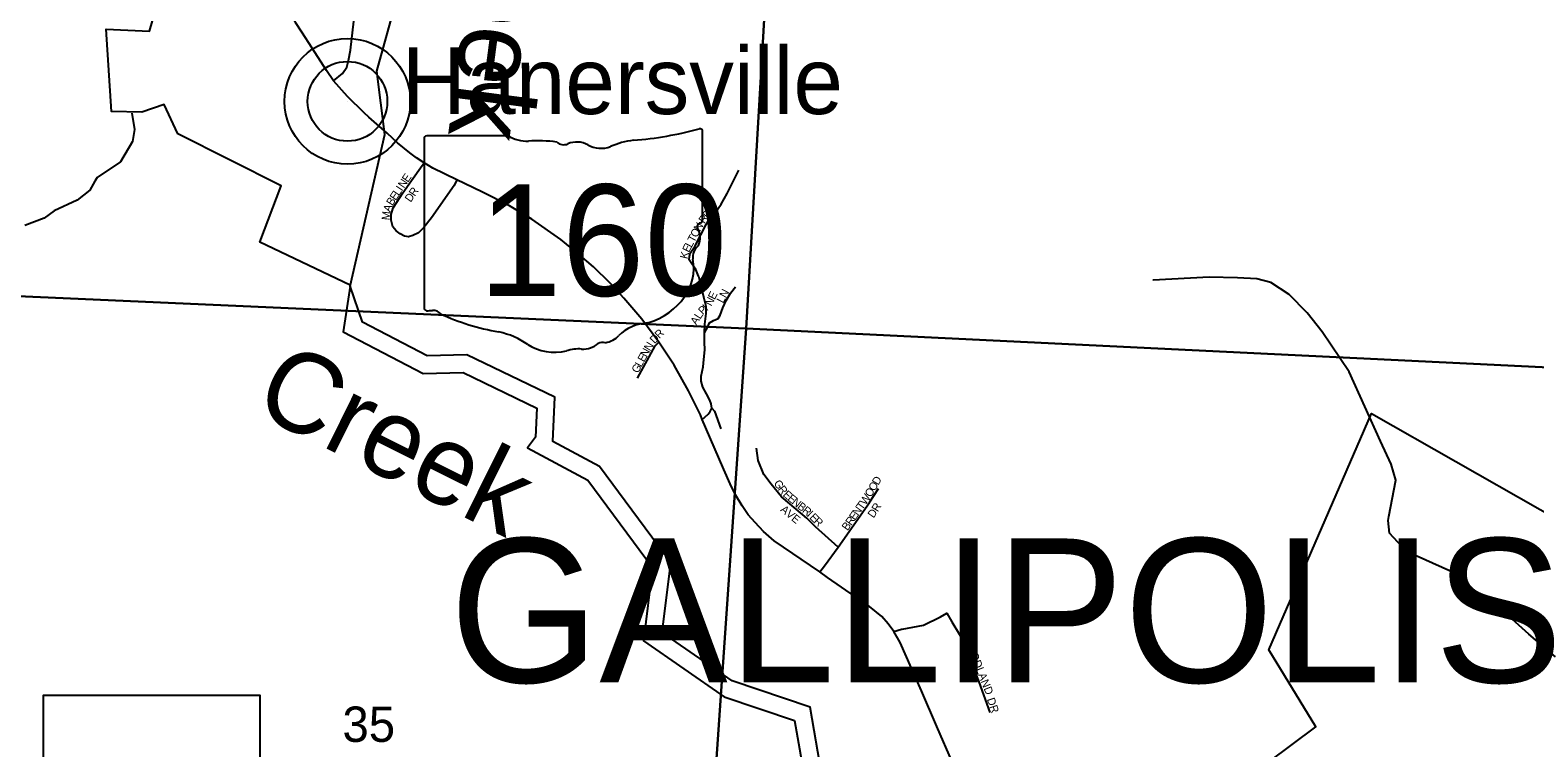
# Model space of a CAD drawing. Extents: x 1878108 to 2183446, y 146837 to 508383.
# Drawn here: x 2047624 to 2057027, y 300413 to 304899 of the extents above; entities that cross this region are included whole.
import ezdxf

# ---------------------------------------------------------------- set-up
doc = ezdxf.new("R2010")
doc.units = 0
for name, color, linetype in [('GM_X_Corporation', 7, 'Continuous'), ('GM_X_County_Road', 7, 'Continuous'), ('GM_X_Minor_River', 7, 'Continuous'), ('GM_X_Minor_River_Text', 7, 'Continuous'), ('GM_X_Section', 7, 'Continuous'), ('GM_X_Section_Text', 7, 'Continuous'), ('GM_X_State_Location', 7, 'Continuous'), ('GM_X_State_Route', 7, 'Continuous'), ('GM_X_State_Shield', 7, 'Continuous'), ('GM_X_Township_Subdivision', 7, 'Continuous'), ('GM_X_Township_Subdivision_Text', 7, 'Continuous'), ('GM_X_Township_Text', 7, 'Continuous'), ('GM_X_Unincorporated', 7, 'Continuous'), ('GM_X_Unincorporated_Location', 7, 'Continuous'), ('GM_X_Unincorporated_Text', 7, 'Continuous')]:
    doc.layers.add(name, color=color, linetype=linetype)

msp = doc.modelspace()

# ---------------------------------------------------------------- linework, layer by layer
at = {"layer": 'GM_X_Corporation'}
for points in [[(2052438.4, 298141.1), (2055657.4, 300543.5), (2055364.1, 301025.2), (2056004.9, 302502.4), (2057587.6, 301603.3)], [(2047707.8, 297853.1), (2047707.7, 300742.9), (2049060.7, 300742.9), (2049060.7, 300300.3)]]:
    msp.add_lwpolyline(points, dxfattribs=at)
at = {"layer": 'GM_X_County_Road'}
msp.add_lwpolyline([(2049520.9, 304582.1), (2049576.5, 304628.2), (2049602.6, 304667.2), (2049614.4, 304708.6), (2049626.2, 304773.7), (2049646.3, 304955.9), (2049667.6, 305345.1), (2049683, 305649.1), (2049706.7, 306075), (2049716.1, 306250.1), (2049732.7, 306522.2), (2049753.9, 306853.8), (2049757.2, 306919.2), (2049764.7, 307070.1), (2049782.4, 307328.9), (2049784.6, 307463.8), (2049773.6, 307593.1), (2049772.1, 307646.4)], dxfattribs=at)
at = {"layer": 'GM_X_Minor_River'}
for points in [[(2049624.7, 303298.8), (2049841.3, 304246.1), (2049790, 304642.5), (2049918.2, 305102.6), (2050045.4, 305183.9), (2050030.3, 305570.6), (2050133.2, 305673.7), (2050185.2, 306139.2), (2050274.7, 307106), (2049923.1, 307624), (2050030, 308031.8), (2050142.8, 308293.3), (2050473.9, 308424.6), (2050730.9, 308841.8), (2050918.4, 309368.5), (2051262.7, 309860.7), (2051316.1, 309921.3), (2051714.1, 310442), (2051728.6, 310861), (2051598.1, 311944.1)], [(2049625.1, 303304.3), (2049060.4, 303573.8), (2049194, 303925.7), (2048546.4, 304250.6), (2048461.8, 304434.2), (2048322.1, 304386.8), (2048133.6, 304391.2), (2048098.8, 304905.9), (2048369.6, 304892.3), (2048427.1, 305087.2), (2048322.9, 305545.3), (2048043, 305791.3), (2047766.3, 305957.2), (2047698.3, 306247.2), (2047932.5, 306575.9), (2047894.8, 306697.9), (2047830, 306749.4), (2047573.1, 306929.5)], [(2048260.7, 304380.1), (2048276.7, 304277.7), (2048264.7, 304203.4), (2048188.6, 304076.8), (2048042.4, 303978.3), (2048028.4, 303954.2), (2047998.4, 303898), (2047918.3, 303835.6), (2047774.2, 303769.2), (2047712.1, 303723), (2047592, 303678.7)], [(2057155.9, 300981.2), (2056989.9, 301123.5), (2056883.8, 301217.8), (2056747.7, 301301.9), (2056507.7, 301512.5), (2056225.5, 301640.6), (2056117.5, 301754.9), (2056109.5, 301833.2), (2056113.5, 301859.3), (2056157.6, 302086.2), (2056129.6, 302186.5), (2056061.6, 302329), (2055865.6, 302762.4), (2055697.6, 303013.1), (2055603.6, 303131.5), (2055491.6, 303245.8), (2055377.5, 303321.9), (2055289.5, 303343.9), (2055169.4, 303349.8), (2054991.3, 303355.6), (2054641, 303337.2), (2054640.4, 303337)], [(2049624.4, 303299.6), (2049580.9, 303013.3), (2050079.4, 302753.2), (2050329.8, 302759.5), (2050789.8, 302537.1), (2050782.1, 302354.7), (2050732.9, 302288.1), (2051108.4, 302087.1), (2051512.4, 301539.6), (2051456.3, 301082.2), (2051962, 300732), (2052400.9, 300583.7), (2052470.3, 300181.5), (2052587.8, 300088.4), (2052896.3, 299946.9), (2052822.2, 299789.9), (2052879.2, 299726.3), (2053136.6, 299664.5), (2053130.2, 299538.2), (2053120.8, 299337.7), (2053342.7, 299079.2), (2053250.6, 298688.9)], [(2053357.7, 298663.7), (2053462.6, 299108.4), (2053232.7, 299376.2), (2053240.1, 299532.8), (2053251, 299750.1), (2052958.3, 299820.4), (2053043.3, 300000.5), (2052645.7, 300182.8), (2052571.6, 300241.6), (2052498.2, 300666.9), (2052011.9, 300831.3), (2051573.6, 301134.8), (2051626.9, 301569.7), (2051182.1, 302172.3), (2050891.1, 302328.2), (2050902.7, 302604.7), (2050353.7, 302870.1), (2050105, 302863.9), (2049701.4, 303074.4), (2049624.4, 303299.6)]]:
    msp.add_lwpolyline(points, dxfattribs=at)
at = {"layer": 'GM_X_Section'}
for points in [[(2052415.9, 308472), (2052098.8, 303033.5), (2046608.5, 303278.4), (2046921.6, 308750.8)], [(2057942.3, 308221.2), (2057916.7, 307664.9), (2057890.5, 307119.5), (2057859.5, 306520.8), (2057833, 305974.8), (2057806.5, 305428.7), (2057761.9, 304523.6), (2057716.2, 303631), (2057671.2, 302762.9), (2052098.8, 303033.5), (2052415.9, 308472)], [(2046608.5, 303278.4), (2052098.8, 303033.5), (2051725.6, 297626.8), (2046305.3, 297866)], [(2057671.2, 302762.9), (2057670.5, 302747.5), (2057409.6, 297482.6), (2057317.7, 297440.2), (2057229.7, 297429.9), (2057149.7, 297419.7), (2057045.8, 297401.3), (2056985.8, 297385.1), (2056929.8, 297374.9), (2051725.6, 297626.8), (2052098.8, 303033.5)]]:
    msp.add_lwpolyline(points, close=True, dxfattribs=at)
at = {"layer": 'GM_X_State_Route'}
for points in [[(2049321.7, 304886.1), (2049283.2, 304946.4), (2049201.5, 305068.3), (2049124.6, 305166.5), (2048998.1, 305304.9), (2048854.9, 305461.3), (2048701.1, 305623.7), (2048439.5, 305905.2)], [(2050338.6, 303940), (2050290.8, 303962.8), (2050140.8, 304036.7), (2050086.4, 304070.2), (2050037.9, 304101.8), (2049997.7, 304131.3), (2049920.8, 304194), (2049855.7, 304254.4), (2049740.1, 304355.2), (2049711.4, 304382.1), (2049607.3, 304483.9), (2049520.9, 304582.1), (2049476, 304645.9), (2049386.1, 304785.5), (2049321.7, 304886.1)], [(2053388.2, 300322.1), (2053288.8, 300546.8), (2053194.2, 300770.4), (2053060.5, 301070.9), (2053020.3, 301139.5), (2052984.8, 301189.2), (2052945.7, 301233), (2052870, 301296.9), (2052606.2, 301478.7), (2052559.1, 301512.5), (2052273.8, 301706.2), (2052207.5, 301765.3), (2052154.3, 301820.9), (2052111.7, 301869.4), (2052073.9, 301925), (2052032.5, 301993.7), (2051998.1, 302063.4), (2051957.9, 302153.4), (2051898.8, 302293), (2051824.2, 302466.3), (2051812.4, 302494), (2051739.1, 302645.5), (2051648, 302804), (2051552.2, 302948.3), (2051445.7, 303092.7), (2051334, 303224.6), (2051248.1, 303317.4), (2051144, 303419.2), (2051046.8, 303502.9), (2050940.5, 303590.7), (2050758.4, 303717.3), (2050619.9, 303800.1), (2050450.8, 303886.5), (2050338.6, 303940)]]:
    msp.add_lwpolyline(points, dxfattribs=at)
at = {"layer": 'GM_X_State_Shield'}
for p, q in [((2050086, 304220.4), (2050086, 303163.7)), ((2050612.8, 304238.6), (2050103.1, 304238.6)), ((2051826.2, 303712), (2051826.2, 304264.7)), ((2051826, 303712.1), (2051826.2, 303712))]:
    msp.add_line(p, q, dxfattribs=at)
for centre, major_axis, start_param, end_param in [((2051206.3, 305679.1), (1845.5, 0), 4.814394, 5.042369), ((2051806.9, 304267), (19.4, 0), 6.141152, 7.989035), ((2050105.9, 304222.6), (20.2, 0), 1.712693, 3.28349), ((2050734.1, 304361.2), (195.5, 0), 4.042523, 4.731795), ((2050799, 303645.4), (702, 0), 1.404758, 1.657858), ((2050958.3, 304228.1), (56.4, 0), 3.836095, 5.185415), ((2051041.2, 304106), (117.3, 0), 0.950623, 2.079405), ((2051192.5, 304273.5), (141.1, 0), 4.081561, 5.145723), ((2051441.7, 303915.8), (371.3, 0), 1.699011, 2.107814), ((2051805.5, 303709.9), (20.7, 0), 5.05454, 6.418171), ((2051821.7, 303671.4), (30, 0), 1.883978, 3.671073), ((2051631, 303601.6), (180, 0), 5.934695, 6.695948), ((2051895.6, 303480.7), (130.9, 0), 2.387724, 3.262537), ((2051309.7, 303410.4), (461.6, 0), 5.101752, 6.440018), ((2050106.1, 303161.4), (20.3, 0), 3.00124, 4.508301), ((2050109.2, 303269.5), (155.2, 0), 4.665946, 4.897461), ((2050141, 303102.8), (56, 0), 0.519207, 1.627899), ((2050847.6, 304052.1), (1332.7, 0), 4.195997, 4.488961), ((2051504.3, 302867.1), (252.8, 0), 1.647645, 2.488434), ((2050450.2, 302689), (417, 0), 0.823519, 1.323587), ((2051184, 303061.3), (149.1, 0), 4.937069, 5.64225), ((2050901.2, 303097.5), (264.6, 0), 4.026481, 4.996735), ((2051054.1, 302732.2), (217.4, 0), 1.495662, 1.94098), ((2051073.4, 303018.4), (141, 0), 4.691044, 5.507374), ((2051201, 302916.1), (39.7, 0), 1.147584, 2.315152)]:
    msp.add_ellipse(centre, major_axis=major_axis, ratio=0.8, start_param=start_param, end_param=end_param, dxfattribs=at)
at = {"layer": 'GM_X_Township_Subdivision'}
for points in [[(2050290.8, 303962.8), (2050273.3, 303927.9), (2050132.6, 303725.6), (2050085.2, 303665.2), (2050050.9, 303632.1), (2050016.6, 303615.5), (2049989.4, 303607.3), (2049962.6, 303611.9), (2049937.4, 303625), (2049911.3, 303643.9), (2049891.2, 303670), (2049879.4, 303711.4), (2049880.6, 303746.9), (2049893.6, 303788.3), (2049952.7, 303881.7), (2050008.3, 303959.8), (2050073.4, 304053.3), (2050086.4, 304070.2)], [(2051800.9, 303362.2), (2051784, 303403.8), (2051759.2, 303438.1), (2051742.6, 303464.1), (2051743.8, 303484.2), (2051748.5, 303504.3), (2051779.3, 303551.7), (2051847.9, 303684.2), (2051870.4, 303719.7), (2051909.5, 303763.5), (2051941.4, 303811.9), (2051980.4, 303877), (2052052.6, 304023.7)], [(2051859.2, 302497.3), (2051860.9, 302498.8), (2051873.9, 302515.4), (2051883.4, 302536.6), (2051879.8, 302562.7), (2051871.6, 302585.2), (2051850.3, 302626.6), (2051827.8, 302666.8), (2051818.3, 302704.6), (2051818.3, 302735.4), (2051829, 302794.5), (2051833.7, 302839.5), (2051840.2, 302901.5), (2051837.3, 302948.3), (2051837.3, 303007.5), (2051840.8, 303061.9), (2051847.9, 303128.2), (2051849.1, 303170.7), (2051834.7, 303231), (2051816, 303309.1), (2051801.8, 303360), (2051800.9, 303362.2)], [(2051837.3, 303007.5), (2051856.2, 303039.4), (2051870.4, 303069), (2051895.2, 303084.4), (2051923.6, 303097.4), (2051936.6, 303117.5), (2051952, 303162.5), (2051974.5, 303208.6), (2052000.5, 303255.9), (2052031.3, 303293.8)], [(2051418.5, 302723.6), (2051529.7, 302925.9), (2051552.2, 302948.3)], [(2051824.2, 302466.3), (2051859.2, 302497.3)], [(2051883.4, 302536.6), (2051901.1, 302517.7), (2051940.2, 302407.7)], [(2052672.5, 301667.1), (2052531.7, 301793.7), (2052478.4, 301848.1), (2052318.7, 301983), (2052254.9, 302061.1), (2052208.7, 302122.6), (2052174.4, 302210.1), (2052163.8, 302285.9)], [(2052872, 301950.6), (2052925.6, 302033.9)], [(2052587.4, 301551.2), (2052672.5, 301667.1), (2052870, 301947.5), (2052872, 301950.6)], [(2052559.1, 301512.5), (2052587.4, 301551.2)], [(2053069.9, 301153.9), (2053073.5, 301154.9), (2053206, 301180.9), (2053312.5, 301231.8), (2053352.7, 301254.3), (2053384.6, 301201), (2053430.8, 301120.6), (2053469.8, 301043.7), (2053500.6, 300957.3), (2053551.4, 300826), (2053620, 300633.2)], [(2053020.3, 301139.5), (2053069.9, 301153.9)]]:
    msp.add_lwpolyline(points, dxfattribs=at)
at = {"layer": 'GM_X_Unincorporated'}
for radius in [392.8, 249]:
    msp.add_circle((2049607.3, 304453.9), radius, dxfattribs=at)
at = {"layer": 'GM_X_Unincorporated_Location'}
msp.add_line((2049607.3, 304453.9), (2049607.3, 304453.9), dxfattribs=at)

# ---------------------------------------------------------------- texts
at = {"layer": 'GM_X_Minor_River_Text'}
for height, rotation, p in [(500.03, 262.51455, (2050468.8, 306017.3)), (499.99, 333.51414, (2049002.4, 302519.2))]:
    msp.add_text('Creek', height=height, rotation=rotation, dxfattribs=at).set_placement(p)
at = {"layer": 'GM_X_Section_Text'}
msp.add_text('35', height=221, rotation=0.00001, dxfattribs=at).set_placement((2049575.9, 300450.3))
at = {"layer": 'GM_X_State_Location'}
for s in ['s', 'r']:
    msp.add_text(s, height=1, dxfattribs=at).set_placement((2050936.5, 303621.8))
msp.add_text('160', height=1, rotation=0.00001, dxfattribs=at).set_placement((2050583.5, 303549.1))
at = {"layer": 'GM_X_State_Shield'}
msp.add_text('160', height=696.1, dxfattribs=at).set_placement((2050427.6, 303238.3))
at = {"layer": 'GM_X_Township_Subdivision_Text'}
for s, rotation, p in [('E', 55.29447, (2049984.6, 303943.8)), ('L', 56.27961, (2049928.5, 303859.8)), ('I', 56.26143, (2049948.1, 303889.1)), ('N', 56.27204, (2049960.3, 303907.4)), ('R', 56.1743, (2050028.1, 303856.3)), ('A', 70.19618, (2049874.5, 303758.5)), ('B', 58.00748, (2049888.2, 303797.3)), ('E', 56.27961, (2049909, 303830.6)), ('D', 54.75194, (2050001.9, 303819.3)), ('M', 84.56484, (2049870.3, 303709.1)), ('R', 54.28159, (2051837.6, 303685.6)), ('D', 52.47005, (2051860.5, 303717.4)), ('T', 61.69924, (2051773.1, 303567.4)), ('O', 61.6948, (2051789.8, 303598.4)), ('N', 61.56747, (2051810.7, 303637.1)), ('K', 75.88953, (2051731.4, 303465.2)), ('E', 63.61819, (2051741.1, 303505.2)), ('L', 61.89537, (2051756.6, 303536.4)), ('E', 63.29025, (2051901.8, 303210.4)), ('LN', 62.10331, (2051954.4, 303188.3)), ('P', 45.96578, (2051828.8, 303116.3)), ('I', 42.3413, (2051852.7, 303141.1)), ('N', 61.68254, (2051880.2, 303170.3)), ('A', 57.25558, (2051787.6, 303051.7)), ('L', 57.24179, (2051811.4, 303088.8)), ('D', 47.73719, (2051527.4, 302935.4)), ('R', 45.00728, (2051556.6, 302967.5)), ('E', 61.38675, (2051460.5, 302820.3)), ('N', 61.38675, (2051477.4, 302851.2)), ('N', 58.65684, (2051498.2, 302889.3)), ('G', 61.38675, (2051422.6, 302750.7)), ('L', 61.38675, (2051443.7, 302789.4)), ('D', 59.03249, (2052923.6, 302051)), ('G', 306.07879, (2052267.6, 302065.8)), ('R', 306.98983, (2052294, 302029.5)), ('E', 316.99871, (2052324.2, 301990.9)), ('O', 58.98305, (2052878.3, 301975.5)), ('O', 59.04866, (2052901, 302013.3)), ('AVE', 320.43739, (2052308, 301895.7)), ('E', 320.85816, (2052352.8, 301964.4)), ('N', 320.8959, (2052380.1, 301942.2)), ('B', 320.92073, (2052414.3, 301914.4)), ('R', 320.69181, (2052445, 301889.5)), ('N', 54.48518, (2052798.3, 301859.8)), ('T', 54.46867, (2052823.9, 301895.6)), ('W', 56.51574, (2052845.5, 301925.9)), ('R', 58.46293, (2052920.7, 301884.3)), ('I', 316.76192, (2052474.9, 301865)), ('E', 314.28505, (2052490.5, 301850.3)), ('R', 315.89513, (2052516.2, 301824)), ('B', 54.47079, (2052731.9, 301766.6)), ('R', 54.48476, (2052754.9, 301798.9)), ('E', 54.51048, (2052777.9, 301831.1)), ('D', 55.41267, (2052894.2, 301845.7)), ('WOODLAND', 291.93023, (2053452.3, 301104.6)), ('DR', 288.43496, (2053602, 300716.9))]:
    msp.add_text(s, height=50, rotation=rotation, dxfattribs=at).set_placement(p)
at = {"layer": 'GM_X_Township_Text'}
msp.add_text('GALLIPOLIS', height=900, rotation=0.00001, dxfattribs=at).set_placement((2050244.7, 300821.6))
at = {"layer": 'GM_X_Unincorporated_Text'}
msp.add_text('Hanersville', height=417, rotation=0.00001, dxfattribs=at).set_placement((2049945.5, 304374.5))

doc.saveas('drawing.dxf')
